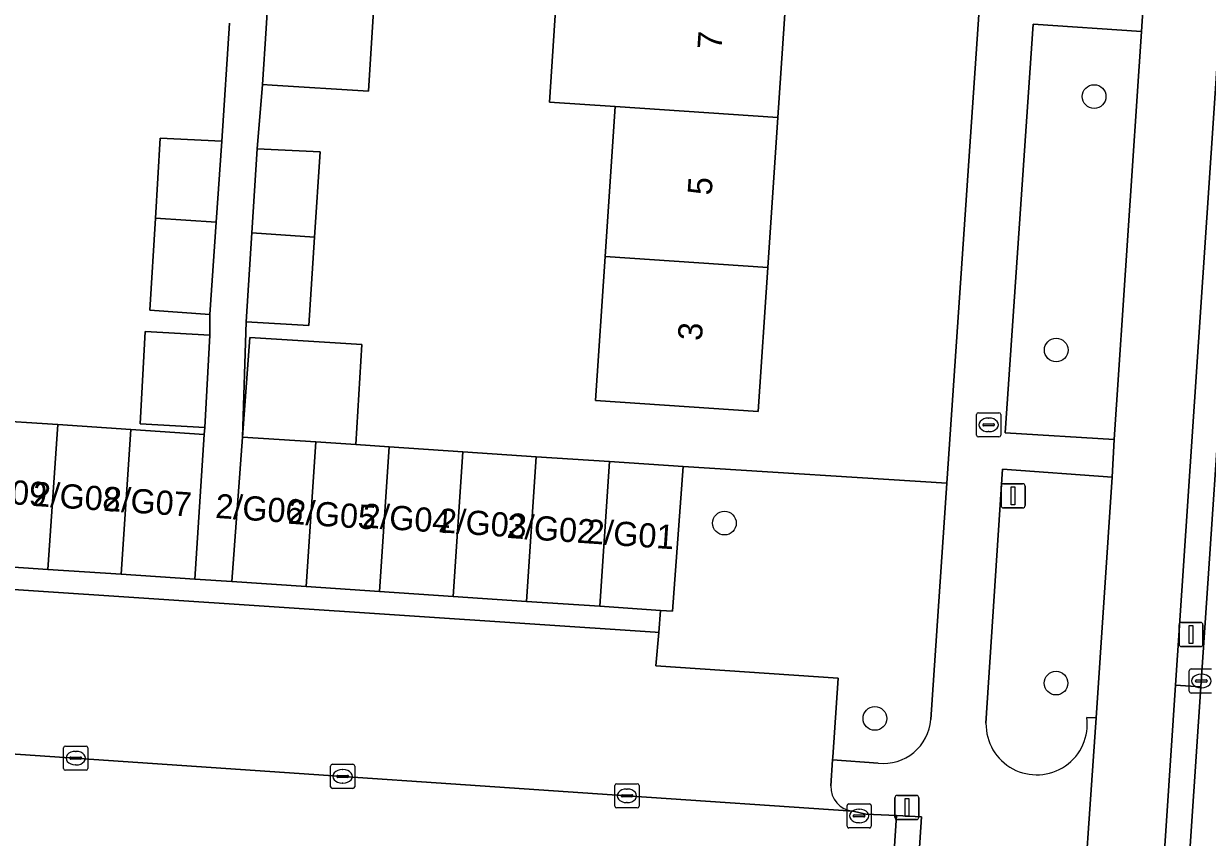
# Model space of a CAD drawing. Extents: x 161848 to 162726, y 385382 to 386521.
# Drawn here: x 161960.24 to 162009.2, y 385610.46 to 385644.09 of the extents above; entities that cross this region are included whole.
import ezdxf

# ---------------------------------------------------------------- set-up
doc = ezdxf.new("R2010")
doc.units = 0
for name, color, linetype in [('IMGEO_Boom', 7, 'Continuous'), ('IMGEO_Brandkraan', 7, 'Continuous'), ('IMGEO_Erf', 7, 'Continuous'), ('IMGEO_Fietspad_gesloten', 7, 'Continuous'), ('IMGEO_Groenvoorziening', 7, 'Continuous'), ('IMGEO_Kolk', 7, 'Continuous'), ('IMGEO_Lichtmast', 7, 'Continuous'), ('IMGEO_Pand', 7, 'Continuous'), ('IMGEO_Pand_nummerreeks', 7, 'Continuous'), ('IMGEO_Parkeervlak_open', 7, 'Continuous'), ('IMGEO_Rijbaan_lokaal_open', 7, 'Continuous'), ('IMGEO_Verkeerseiland_open', 7, 'Continuous'), ('IMGEO_Voetpad_open', 7, 'Continuous')]:
    doc.layers.add(name, color=color, linetype=linetype)

msp = doc.modelspace()

# ---------------------------------------------------------------- linework, layer by layer
at = {"layer": 'IMGEO_Boom'}
for centre in [(162004.522, 385641.075), (162002.953, 385630.598), (161989.23, 385623.445), (162002.946, 385616.832), (161995.453, 385615.371)]:
    msp.add_circle(centre, 0.489, dxfattribs=at)
at = {"layer": 'IMGEO_Brandkraan'}
for p, q in [((161999.659, 385627.081), (161999.659, 385627.933)), ((161999.734, 385628.007), (162000.586, 385628.007)), ((162000.66, 385627.933), (162000.66, 385627.081)), ((161999.918, 385627.501), (161999.918, 385627.513)), ((162000.356, 385627.464), (161999.958, 385627.464)), ((161999.961, 385627.55), (162000.359, 385627.55)), ((162000.147, 385627.787), (162000.172, 385627.787)), ((162000.402, 385627.513), (162000.402, 385627.501)), ((162000.586, 385627.007), (161999.734, 385627.007)), ((162000.17, 385627.227), (162000.145, 385627.227))]:
    msp.add_line(p, q, dxfattribs=at)
for points in [[(161999.659, 385627.081), (161999.659, 385627.933)], [(161999.734, 385628.007), (162000.586, 385628.007)], [(162000.66, 385627.933), (162000.66, 385627.081)], [(162000.586, 385627.007), (161999.734, 385627.007)]]:
    msp.add_lwpolyline(points, dxfattribs=at)
for centre, radius, start, end in [((161999.736, 385627.931), 0.0765, 91.552, 178.448), ((161999.736, 385627.931), 0.0765, 91.552, 178.448), ((162000.584, 385627.931), 0.0765, 1.552, 88.448), ((162000.584, 385627.931), 0.0765, 1.552, 88.448), ((161999.958, 385627.51), 0.0403, 85.8775, 175.7526), ((161999.955, 385627.5), 0.0366, 178.938, 274.7102), ((162000.359, 385627.507), 0.043, 264.8664, 352.4533), ((162000.363, 385627.512), 0.0386, 1.7309, 96.639), ((161999.736, 385627.083), 0.0765, 181.552, 268.448), ((161999.736, 385627.083), 0.0765, 181.552, 268.448), ((162000.584, 385627.083), 0.0765, 271.552, 358.448), ((162000.584, 385627.083), 0.0765, 271.552, 358.448)]:
    msp.add_arc(centre, radius, start, end, dxfattribs=at)
for centre, major_axis, ratio, start_param, end_param in [((162000.146, 385627.507), (-0.387, 0.002), 0.722429, 4.712389, 7.853982), ((162000.171, 385627.507), (-0.39, 0.002), 0.717154, 1.570796, 4.712389)]:
    msp.add_ellipse(centre, major_axis=major_axis, ratio=ratio, start_param=start_param, end_param=end_param, dxfattribs=at)
at = {"layer": 'IMGEO_Erf'}
for points in [[(161994.282, 385682.228), (161993.872, 385676.165), (161993.469, 385670.192), (161993.061, 385664.146), (161992.659, 385658.183), (161992.252, 385652.159), (161991.845, 385646.136), (161991.445, 385640.212), (161991.027, 385634.016), (161990.625, 385628.06), (161983.891, 385628.515), (161984.292, 385634.466), (161984.71, 385640.662), (161981.988, 385640.844), (161982.383, 385646.768), (161985.11, 385646.586), (161985.517, 385652.61), (161985.923, 385658.633), (161986.325, 385664.597), (161986.733, 385670.642), (161987.136, 385676.616), (161987.545, 385682.678)], [(161974.873, 385647.271), (161974.503, 385641.297), (161970.529, 385641.543), (161970.127, 385641.568), (161969.896, 385638.909), (161972.51, 385638.788), (161972.28, 385635.269), (161972.041, 385631.607), (161969.453, 385631.765), (161969.291, 385627.004), (161969.592, 385631.114), (161974.234, 385630.831), (161973.981, 385626.689), (161975.367, 385626.596), (161978.405, 385626.392), (161981.443, 385626.189), (161984.481, 385625.985), (161987.519, 385625.781), (161998.429, 385625.093), (162000.549, 385656.175)], [(161958.618, 385627.72), (161961.651, 385627.517), (161964.683, 385627.314), (161967.716, 385627.11), (161967.734, 385627.396), (161965.06, 385627.546), (161965.276, 385631.366), (161967.949, 385631.215), (161967.95, 385632.074), (161965.464, 385632.243), (161965.694, 385636.054), (161965.894, 385639.362), (161968.444, 385639.229), (161968.762, 385644.112)]]:
    msp.add_lwpolyline(points, dxfattribs=at)
at = {"layer": 'IMGEO_Fietspad_gesloten'}
msp.add_lwpolyline([(162013.158, 385743.949), (162010.873, 385709.146), (162010.549, 385704.218), (162010.295, 385700.348), (162010.217, 385699.151), (162008.977, 385680.053), (162008.886, 385678.416), (162007.821, 385663.003), (162007.424, 385657.272), (162006.576, 385645.271), (162006.478, 385643.76), (162005.344, 385626.899), (162005.265, 385625.346), (162004.604, 385615.402), (162004.294, 385610.839), (162003.948, 385605.742), (162007.138, 385605.527), (162007.893, 385616.747), (162013.268, 385696.929), (162014.399, 385713.867), (162016.417, 385744.964)], dxfattribs=at)
at = {"layer": 'IMGEO_Groenvoorziening'}
msp.add_lwpolyline([(162006.478, 385643.76), (162001.996, 385644.061), (162000.837, 385627.179), (162005.344, 385626.899)], close=True, dxfattribs=at)
for points in [[(161997.763, 385615.324), (161998.429, 385625.093), (161987.519, 385625.781), (161987.081, 385619.806), (161986.585, 385619.839), (161986.511, 385618.928), (161986.398, 385617.549), (161993.932, 385617.041), (161993.709, 385613.769), (161993.701, 385613.657), (161995.595, 385613.52)], [(162004.222, 385615.406), (162004.604, 385615.402), (162005.265, 385625.346), (162000.737, 385625.677), (162000.049, 385615.172)]]:
    msp.add_lwpolyline(points, dxfattribs=at)
for centre, radius, start, end in [((161995.802, 385615.476), 1.967, 263.9595, 355.5684), ((162002.144, 385615.138), 2.095, 179.0695, 7.3495)]:
    msp.add_arc(centre, radius, start, end, dxfattribs=at)
at = {"layer": 'IMGEO_Kolk'}
for p, q in [((162008.455, 385616.494), (162008.455, 385617.346)), ((162008.53, 385617.42), (162009.382, 385617.42)), ((162008.943, 385617.2), (162008.968, 385617.2)), ((162008.714, 385616.914), (162008.714, 385616.926)), ((162009.152, 385616.877), (162008.754, 385616.877)), ((162008.757, 385616.963), (162009.155, 385616.963)), ((162009.198, 385616.926), (162009.198, 385616.914)), ((162009.382, 385616.42), (162008.53, 385616.42)), ((162008.966, 385616.64), (162008.941, 385616.64)), ((161961.972, 385614.232), (161962.824, 385614.232)), ((161961.897, 385613.306), (161961.897, 385614.158)), ((161962.156, 385613.726), (161962.156, 385613.738)), ((161962.199, 385613.775), (161962.597, 385613.775)), ((161962.385, 385614.012), (161962.41, 385614.012)), ((161962.64, 385613.738), (161962.64, 385613.726)), ((161962.898, 385614.158), (161962.898, 385613.306)), ((161962.824, 385613.232), (161961.972, 385613.232)), ((161962.594, 385613.689), (161962.196, 385613.689)), ((161962.408, 385613.452), (161962.383, 385613.452)), ((161972.938, 385612.55), (161972.938, 385613.402)), ((161973.013, 385613.476), (161973.865, 385613.476)), ((161973.426, 385613.256), (161973.451, 385613.256)), ((161973.939, 385613.402), (161973.939, 385612.55)), ((161973.197, 385612.97), (161973.197, 385612.982)), ((161973.635, 385612.933), (161973.237, 385612.933)), ((161973.24, 385613.019), (161973.638, 385613.019)), ((161973.681, 385612.982), (161973.681, 385612.97)), ((161973.865, 385612.476), (161973.013, 385612.476)), ((161973.449, 385612.696), (161973.424, 385612.696)), ((161984.696, 385611.748), (161984.696, 385612.6)), ((161984.771, 385612.674), (161985.623, 385612.674)), ((161985.184, 385612.454), (161985.209, 385612.454)), ((161985.697, 385612.6), (161985.697, 385611.748)), ((161984.955, 385612.168), (161984.955, 385612.18)), ((161985.393, 385612.131), (161984.995, 385612.131)), ((161984.998, 385612.217), (161985.396, 385612.217)), ((161985.207, 385611.894), (161985.182, 385611.894)), ((161985.439, 385612.18), (161985.439, 385612.168)), ((161994.301, 385610.918), (161994.301, 385611.77)), ((161994.376, 385611.844), (161995.228, 385611.844)), ((161995.302, 385611.77), (161995.302, 385610.918)), ((161985.623, 385611.674), (161984.771, 385611.674)), ((161994.56, 385611.338), (161994.56, 385611.35)), ((161994.998, 385611.301), (161994.6, 385611.301)), ((161994.603, 385611.387), (161995.001, 385611.387)), ((161994.789, 385611.624), (161994.814, 385611.624)), ((161995.044, 385611.35), (161995.044, 385611.338)), ((161995.228, 385610.844), (161994.376, 385610.844)), ((161994.812, 385611.064), (161994.787, 385611.064))]:
    msp.add_line(p, q, dxfattribs=at)
for points in [[(162008.455, 385616.494), (162008.455, 385617.346)], [(162008.53, 385617.42), (162009.382, 385617.42)], [(162009.382, 385616.42), (162008.53, 385616.42)], [(161961.972, 385614.232), (161962.824, 385614.232)], [(161961.897, 385613.306), (161961.897, 385614.158)], [(161962.898, 385614.158), (161962.898, 385613.306)], [(161962.824, 385613.232), (161961.972, 385613.232)], [(161972.938, 385612.55), (161972.938, 385613.402)], [(161973.013, 385613.476), (161973.865, 385613.476)], [(161973.939, 385613.402), (161973.939, 385612.55)], [(161973.865, 385612.476), (161973.013, 385612.476)], [(161984.696, 385611.748), (161984.696, 385612.6)], [(161984.771, 385612.674), (161985.623, 385612.674)], [(161985.697, 385612.6), (161985.697, 385611.748)], [(161994.301, 385610.918), (161994.301, 385611.77)], [(161994.376, 385611.844), (161995.228, 385611.844)], [(161995.302, 385611.77), (161995.302, 385610.918)], [(161985.623, 385611.674), (161984.771, 385611.674)], [(161995.228, 385610.844), (161994.376, 385610.844)]]:
    msp.add_lwpolyline(points, dxfattribs=at)
for centre, radius, start, end in [((162008.532, 385617.344), 0.0765, 91.552, 178.448), ((162008.532, 385617.344), 0.0765, 91.552, 178.448), ((162008.754, 385616.923), 0.0403, 85.8775, 175.7526), ((162008.751, 385616.913), 0.0366, 178.938, 274.7102), ((162009.155, 385616.92), 0.043, 264.8664, 352.4533), ((162009.159, 385616.925), 0.0386, 1.7309, 96.639), ((162008.532, 385616.496), 0.0765, 181.552, 268.448), ((162008.532, 385616.496), 0.0765, 181.552, 268.448), ((161961.974, 385614.156), 0.0765, 91.552, 178.448), ((161961.974, 385614.156), 0.0765, 91.552, 178.448), ((161962.822, 385614.156), 0.0765, 1.552, 88.448), ((161962.822, 385614.156), 0.0765, 1.552, 88.448), ((161962.196, 385613.735), 0.0403, 85.8775, 175.7526), ((161962.193, 385613.725), 0.0366, 178.938, 274.7102), ((161962.597, 385613.732), 0.043, 264.8664, 352.4533), ((161962.601, 385613.737), 0.0386, 1.7309, 96.639), ((161961.974, 385613.308), 0.0765, 181.552, 268.448), ((161961.974, 385613.308), 0.0765, 181.552, 268.448), ((161962.822, 385613.308), 0.0765, 271.552, 358.448), ((161962.822, 385613.308), 0.0765, 271.552, 358.448), ((161973.015, 385613.4), 0.0765, 91.552, 178.448), ((161973.015, 385613.4), 0.0765, 91.552, 178.448), ((161973.863, 385613.4), 0.0765, 1.552, 88.448), ((161973.863, 385613.4), 0.0765, 1.552, 88.448), ((161973.237, 385612.979), 0.0403, 85.8775, 175.7526), ((161973.234, 385612.969), 0.0366, 178.938, 274.7102), ((161973.638, 385612.976), 0.043, 264.8664, 352.4533), ((161973.642, 385612.981), 0.0386, 1.7309, 96.639), ((161973.015, 385612.552), 0.0765, 181.552, 268.448), ((161973.015, 385612.552), 0.0765, 181.552, 268.448), ((161973.863, 385612.552), 0.0765, 271.552, 358.448), ((161973.863, 385612.552), 0.0765, 271.552, 358.448), ((161984.773, 385612.598), 0.0765, 91.552, 178.448), ((161984.773, 385612.598), 0.0765, 91.552, 178.448), ((161985.621, 385612.598), 0.0765, 1.552, 88.448), ((161985.621, 385612.598), 0.0765, 1.552, 88.448), ((161984.995, 385612.177), 0.0403, 85.8775, 175.7526), ((161984.992, 385612.167), 0.0366, 178.938, 274.7102), ((161985.396, 385612.174), 0.043, 264.8664, 352.4533), ((161985.4, 385612.179), 0.0386, 1.7309, 96.639), ((161994.378, 385611.768), 0.0765, 91.552, 178.448), ((161994.378, 385611.768), 0.0765, 91.552, 178.448), ((161995.226, 385611.768), 0.0765, 1.552, 88.448), ((161995.226, 385611.768), 0.0765, 1.552, 88.448), ((161984.773, 385611.75), 0.0765, 181.552, 268.448), ((161984.773, 385611.75), 0.0765, 181.552, 268.448), ((161985.621, 385611.75), 0.0765, 271.552, 358.448), ((161985.621, 385611.75), 0.0765, 271.552, 358.448), ((161994.6, 385611.347), 0.0403, 85.8775, 175.7526), ((161994.597, 385611.337), 0.0366, 178.938, 274.7102), ((161995.001, 385611.344), 0.043, 264.8664, 352.4533), ((161995.005, 385611.349), 0.0386, 1.7309, 96.639), ((161994.378, 385610.92), 0.0765, 181.552, 268.448), ((161994.378, 385610.92), 0.0765, 181.552, 268.448), ((161995.226, 385610.92), 0.0765, 271.552, 358.448), ((161995.226, 385610.92), 0.0765, 271.552, 358.448)]:
    msp.add_arc(centre, radius, start, end, dxfattribs=at)
for centre, major_axis, ratio, start_param, end_param in [((162008.942, 385616.92), (-0.387, 0.002), 0.722429, 4.712389, 7.853982), ((162008.967, 385616.92), (-0.39, 0.002), 0.717154, 1.570796, 4.712389), ((161962.384, 385613.732), (-0.387, 0.002), 0.722429, 4.712389, 7.853982), ((161962.409, 385613.732), (-0.39, 0.002), 0.717154, 1.570796, 4.712389), ((161973.425, 385612.976), (-0.387, 0.002), 0.722429, 4.712389, 7.853982), ((161973.45, 385612.976), (-0.39, 0.002), 0.717154, 1.570796, 4.712389), ((161985.183, 385612.174), (-0.387, 0.002), 0.722429, 4.712389, 7.853982), ((161985.208, 385612.174), (-0.39, 0.002), 0.717154, 1.570796, 4.712389), ((161994.788, 385611.344), (-0.387, 0.002), 0.722429, 4.712389, 7.853982), ((161994.813, 385611.344), (-0.39, 0.002), 0.717154, 1.570796, 4.712389)]:
    msp.add_ellipse(centre, major_axis=major_axis, ratio=ratio, start_param=start_param, end_param=end_param, dxfattribs=at)
at = {"layer": 'IMGEO_Lichtmast'}
for p, q in [((162000.775, 385625.07), (162001.565, 385625.07)), ((162001.565, 385625.07), (162000.775, 385625.07)), ((162000.675, 385624.17), (162000.675, 385624.97)), ((162000.675, 385624.97), (162000.675, 385624.17)), ((162001.665, 385624.97), (162001.665, 385624.17)), ((162001.665, 385624.17), (162001.665, 385624.97)), ((162001.565, 385624.07), (162000.775, 385624.07)), ((162000.775, 385624.07), (162001.565, 385624.07)), ((162008.033, 385618.442), (162008.033, 385619.242)), ((162008.033, 385619.242), (162008.033, 385618.442)), ((162008.133, 385619.342), (162008.923, 385619.342)), ((162008.923, 385619.342), (162008.133, 385619.342)), ((162009.023, 385619.242), (162009.023, 385618.442)), ((162009.023, 385618.442), (162009.023, 385619.242)), ((162008.923, 385618.342), (162008.133, 385618.342)), ((162008.133, 385618.342), (162008.923, 385618.342)), ((161996.282, 385611.293), (161996.282, 385612.093)), ((161996.282, 385612.093), (161996.282, 385611.293)), ((161996.382, 385612.193), (161997.172, 385612.193)), ((161997.172, 385612.193), (161996.382, 385612.193)), ((161997.272, 385612.093), (161997.272, 385611.293)), ((161997.272, 385611.293), (161997.272, 385612.093)), ((161997.172, 385611.193), (161996.382, 385611.193)), ((161996.382, 385611.193), (161997.172, 385611.193))]:
    msp.add_line(p, q, dxfattribs=at)
for points in [[(162001.095, 385624.945), (162001.245, 385624.945), (162001.245, 385624.195), (162001.095, 385624.195), (162001.095, 385624.945)], [(162008.453, 385619.217), (162008.603, 385619.217), (162008.603, 385618.467), (162008.453, 385618.467), (162008.453, 385619.217)], [(161996.702, 385612.068), (161996.852, 385612.068), (161996.852, 385611.318), (161996.702, 385611.318), (161996.702, 385612.068)]]:
    msp.add_lwpolyline(points, dxfattribs=at)
for centre, start, end in [((162000.775, 385624.97), 90, 180), ((162000.775, 385624.97), 90, 180), ((162001.565, 385624.97), 0, 90), ((162001.565, 385624.97), 360, 90), ((162000.775, 385624.17), 180, 270), ((162000.775, 385624.17), 180, 270), ((162001.565, 385624.17), 270, 0), ((162001.565, 385624.17), 270, 0), ((162008.133, 385619.242), 90, 180), ((162008.133, 385619.242), 90, 180), ((162008.923, 385619.242), 0, 90), ((162008.923, 385619.242), 360, 90), ((162008.133, 385618.442), 180, 270), ((162008.133, 385618.442), 180, 270), ((162008.923, 385618.442), 270, 0), ((162008.923, 385618.442), 270, 0), ((161996.382, 385612.093), 90, 180), ((161996.382, 385612.093), 90, 180), ((161997.172, 385612.093), 0, 90), ((161997.172, 385612.093), 360, 90), ((161996.382, 385611.293), 180, 270), ((161996.382, 385611.293), 180, 270), ((161997.172, 385611.293), 270, 0), ((161997.172, 385611.293), 270, 0)]:
    msp.add_arc(centre, 0.1, start, end, dxfattribs=at)
at = {"layer": 'IMGEO_Pand'}
for points in [[(161973.098, 385647.389), (161970.499, 385647.562), (161970.271, 385643.885), (161970.127, 385641.568), (161970.529, 385641.543), (161974.503, 385641.297), (161974.873, 385647.271)], [(161991.845, 385646.136), (161985.11, 385646.586), (161982.383, 385646.768), (161981.988, 385640.844), (161984.71, 385640.662), (161991.445, 385640.212)], [(161991.445, 385640.212), (161984.71, 385640.662), (161984.292, 385634.466), (161991.027, 385634.016)], [(161968.444, 385639.229), (161965.894, 385639.362), (161965.694, 385636.054), (161968.213, 385635.883)], [(161972.51, 385638.788), (161969.896, 385638.909), (161969.681, 385635.442), (161972.28, 385635.269)], [(161965.464, 385632.243), (161967.95, 385632.074), (161968.213, 385635.883), (161965.694, 385636.054)], [(161969.453, 385631.765), (161972.041, 385631.607), (161972.28, 385635.269), (161969.681, 385635.442)], [(161983.891, 385628.515), (161990.625, 385628.06), (161991.027, 385634.016), (161984.292, 385634.466)], [(161967.734, 385627.396), (161967.949, 385631.215), (161965.276, 385631.366), (161965.06, 385627.546)], [(161969.291, 385627.004), (161972.329, 385626.8), (161973.981, 385626.689), (161974.234, 385630.831), (161969.592, 385631.114)], [(161961.249, 385621.534), (161961.651, 385627.517), (161958.618, 385627.72), (161958.216, 385621.737)], [(161964.282, 385621.33), (161964.683, 385627.314), (161961.651, 385627.517), (161961.249, 385621.534)], [(161967.324, 385621.126), (161967.716, 385627.11), (161964.683, 385627.314), (161964.282, 385621.33)], [(161971.928, 385620.823), (161972.329, 385626.8), (161969.291, 385627.004), (161968.853, 385621.029)], [(161975.367, 385626.596), (161973.981, 385626.689), (161972.329, 385626.8), (161971.928, 385620.823), (161974.966, 385620.619)], [(161978.004, 385620.415), (161978.405, 385626.392), (161975.367, 385626.596), (161974.966, 385620.619)], [(161981.042, 385620.211), (161981.443, 385626.189), (161978.405, 385626.392), (161978.004, 385620.415)], [(161984.08, 385620.007), (161984.481, 385625.985), (161981.443, 385626.189), (161981.042, 385620.211)], [(161986.585, 385619.839), (161987.081, 385619.806), (161987.519, 385625.781), (161984.481, 385625.985), (161984.08, 385620.007)]]:
    msp.add_lwpolyline(points, close=True, dxfattribs=at)
at = {"layer": 'IMGEO_Parkeervlak_open'}
for points in [[(161993.932, 385617.041), (161986.398, 385617.549), (161986.511, 385618.928), (161986.369, 385618.938), (161949.651, 385621.38), (161949.284, 385616.611)], [(161993.629, 385612.588), (161993.701, 385613.657), (161993.709, 385613.769), (161993.932, 385617.041)], [(161947.158, 385614.769), (161985.197, 385612.173), (161994.548, 385611.545)]]:
    msp.add_lwpolyline(points, dxfattribs=at)
msp.add_arc((161994.629, 385612.543), 1.001, 177.419, 265.3484, dxfattribs=at)
at = {"layer": 'IMGEO_Rijbaan_lokaal_open'}
for points in [[(162014.09, 385602.491), (162015.218, 385619.015), (162016.148, 385632.865), (162010.05, 385633.182), (162008.94, 385616.682), (162007.797, 385599.605), (162007.58, 385596.315), (162007.244, 385591.241), (162006.746, 385583.864), (162005.598, 385566.94), (162003.18, 385531.527), (162002.072, 385515.337), (161999.911, 385483.524), (161999.357, 385475.567), (161997.814, 385452.783), (161997.678, 385450.723)], [(161939.176, 385621.222), (161934.124, 385621.658), (161933.385, 385610.532), (161943.229, 385609.934), (161996.016, 385606.302), (161996.35, 385611.357)], [(161996.35, 385611.357), (161995.075, 385611.421), (161994.548, 385611.545), (161985.197, 385612.173), (161947.158, 385614.769), (161944.695, 385614.932)]]:
    msp.add_lwpolyline(points, dxfattribs=at)
msp.add_lwpolyline([(161996.35, 385611.357), (161996.016, 385606.302), (161997.056, 385606.216), (161997.378, 385611.304)], close=True, dxfattribs=at)
at = {"layer": 'IMGEO_Verkeerseiland_open'}
msp.add_lwpolyline([(162014.322, 385696.873), (162013.268, 385696.929), (162007.893, 385616.747), (162008.94, 385616.682), (162010.05, 385633.182), (162011.334, 385651.941)], close=True, dxfattribs=at)
at = {"layer": 'IMGEO_Voetpad_open'}
for points in [[(162002.926, 385709.929), (162003.231, 385709.718), (162004.267, 385709.569), (162003.93, 385704.551), (162003.78, 385704.564), (162003.492, 385700.232), (162000.908, 385661.369), (162001.053, 385661.34), (162000.699, 385656.226), (162000.549, 385656.175), (161998.429, 385625.093), (161997.763, 385615.324)], [(162000.049, 385615.172), (162000.737, 385625.677), (162005.265, 385625.346), (162005.344, 385626.899), (162000.837, 385627.179), (162001.996, 385644.061), (162006.478, 385643.76), (162006.576, 385645.271), (162002.106, 385645.574), (162002.921, 385657.57), (162007.424, 385657.272), (162007.821, 385663.003), (162003.308, 385663.277), (162004.365, 385678.704), (162008.886, 385678.416), (162008.977, 385680.053), (162004.472, 385680.234), (162005.838, 385700.634)], [(161968.762, 385644.112), (161968.444, 385639.229), (161968.213, 385635.883), (161967.95, 385632.074), (161967.949, 385631.215), (161967.734, 385627.396), (161967.716, 385627.11), (161967.324, 385621.126), (161968.853, 385621.029), (161969.291, 385627.004), (161969.453, 385631.765), (161969.681, 385635.442), (161969.896, 385638.909), (161970.127, 385641.568), (161970.271, 385643.885), (161970.499, 385647.562)], [(161994.548, 385611.545), (161995.075, 385611.421), (161996.35, 385611.357), (161997.378, 385611.304), (161997.056, 385606.216), (162003.948, 385605.742), (162004.294, 385610.839), (162004.604, 385615.402), (162004.222, 385615.406)], [(161995.595, 385613.52), (161993.701, 385613.657), (161993.629, 385612.588)]]:
    msp.add_lwpolyline(points, dxfattribs=at)
for points in [[(161986.585, 385619.839), (161984.08, 385620.007), (161981.042, 385620.211), (161978.004, 385620.415), (161974.966, 385620.619), (161971.928, 385620.823), (161968.853, 385621.029), (161967.324, 385621.126), (161964.282, 385621.33), (161961.249, 385621.534), (161958.216, 385621.737), (161955.184, 385621.941), (161952.151, 385622.144), (161949.722, 385622.307), (161949.651, 385621.38), (161986.369, 385618.938), (161986.511, 385618.928)], [(162008.94, 385616.682), (162007.893, 385616.747), (162007.138, 385605.527), (162006.744, 385599.673), (162007.797, 385599.605)]]:
    msp.add_lwpolyline(points, close=True, dxfattribs=at)
for centre, radius, start, end in [((161995.802, 385615.476), 1.967, 263.9595, 355.5684), ((162002.144, 385615.138), 2.095, 179.0695, 7.3495), ((161994.629, 385612.543), 1.001, 177.419, 265.3484)]:
    msp.add_arc(centre, radius, start, end, dxfattribs=at)

# ---------------------------------------------------------------- texts
at = {"layer": 'IMGEO_Pand_nummerreeks'}
for s, rotation, p in [('7', 86.138, (161989.106, 385642.988)), ('5', 86.138, (161988.7, 385636.975)), ('3', 86.138, (161988.295, 385630.962)), ('2/G09', 356.0818, (161957.543, 385624.378)), ('2/G08', 356.0818, (161960.588, 385624.159)), ('2/G07', 356.0818, (161963.523, 385623.961)), ('2/G06', 356.0818, (161968.15, 385623.663)), ('2/G05', 356.081, (161971.148, 385623.425)), ('2/G04', 356.0818, (161974.226, 385623.266)), ('2/G03', 356.0818, (161977.383, 385623.067)), ('2/G02', 356.0818, (161980.208, 385622.837)), ('2/G01', 356.0818, (161983.492, 385622.612))]:
    msp.add_text(s, height=1, rotation=rotation, dxfattribs=at).set_placement(p)

doc.saveas('drawing.dxf')
